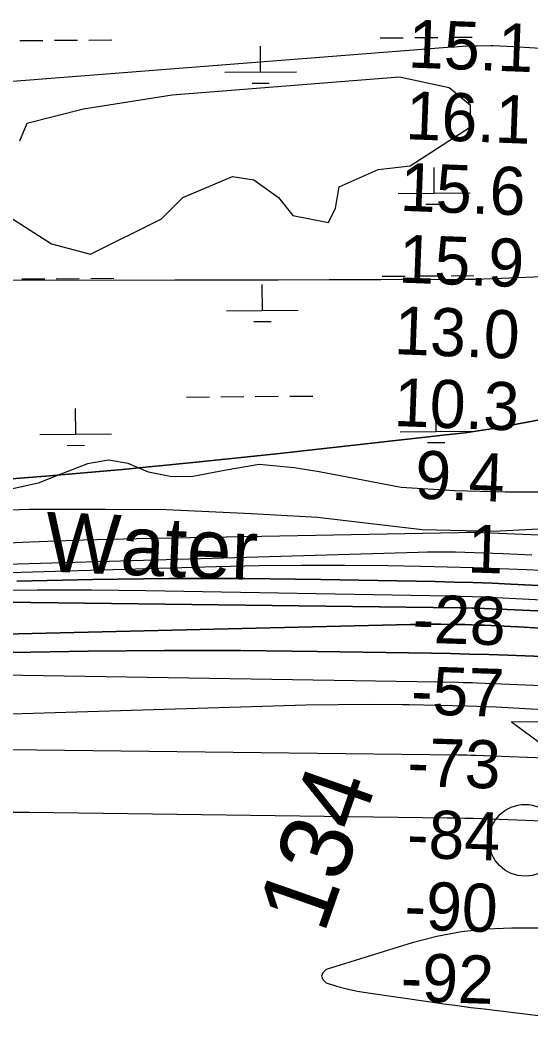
# Model space of a CAD drawing. Extents: x 3540316 to 3578335, y 553172 to 578787.
# Drawn here: x 3546126 to 3546837, y 565814 to 567208 of the extents above; entities that cross this region are included whole.
import ezdxf

# ---------------------------------------------------------------- set-up
doc = ezdxf.new("R2010")
doc.units = 0
for name, color, linetype in [('V-CHAN-NAID', 7, 'Continuous'), ('V-RIVR-EDGE', 7, 'Continuous'), ('V-RIVR-IDEN', 7, 'Continuous'), ('V-RIVR-MILE', 7, 'Continuous'), ('V-RIVR-RANG', 7, 'Continuous'), ('V-TOPO-DPTH', 7, 'Continuous'), ('V-TOPO-MAJR', 7, 'Continuous'), ('V-TOPO-MINR', 7, 'Continuous'), ('V-TOPO-WATR', 7, 'Continuous'), ('V-WETL-SWMP', 7, 'Continuous')]:
    doc.layers.add(name, color=color, linetype=linetype)

msp = doc.modelspace()

# ---------------------------------------------------------------- linework, layer by layer
at = {"layer": 'V-CHAN-NAID'}
msp.add_lwpolyline([(3546887, 566229.1), (3546810.5, 566229.7), (3546872, 566184.3)], dxfattribs=at)
at = {"layer": 'V-RIVR-EDGE'}
msp.add_lwpolyline([(3547564.9, 566487.3), (3547538, 566489.2), (3547500.6, 566487.4), (3547465.6, 566486.9), (3547417.2, 566484), (3547335.7, 566475), (3547277.5, 566472.7), (3547236.4, 566468.5), (3547157.4, 566479.1), (3547082.7, 566484.8), (3546918.5, 566501.7), (3546785.5, 566494.7), (3546685.7, 566497.4), (3546539.9, 566514.3), (3546448, 566519.5), (3546329.1, 566525.3), (3546245.2, 566525.5), (3546138.6, 566525.7), (3545988.4, 566520.6)], dxfattribs=at)
at = {"layer": 'V-RIVR-MILE'}
msp.add_circle((3546829.2, 566064.6), 50, dxfattribs=at)
at = {"layer": 'V-TOPO-DPTH'}
for points in [[(3546053.9, 566563.7), (3546161.4, 566572.2), (3546268.7, 566581.4), (3546375.9, 566591.9), (3546483.1, 566603.2), (3546727.7, 566630.4), (3546745.9, 566632.6), (3546764, 566635.1), (3546782.1, 566638.1), (3546800.1, 566641.3), (3546849.2, 566650.6)], [(3546838.8, 566462.1), (3546818.6, 566463), (3546798.5, 566463.8), (3546784.2, 566464.4), (3546771.2, 566464.9), (3546758.2, 566465.3), (3546745.2, 566465.6), (3546732.2, 566465.9), (3546719.2, 566466), (3546706.2, 566466), (3546693.2, 566465.9), (3546680.2, 566465.6), (3545898.5, 566442.7)], [(3546838.8, 566462.1), (3546818.6, 566463), (3546798.5, 566463.8), (3546784.2, 566464.4), (3546771.2, 566464.9), (3546758.2, 566465.3), (3546745.2, 566465.6), (3546732.2, 566465.9), (3546719.2, 566466), (3546706.2, 566466), (3546693.2, 566465.9), (3546680.2, 566465.6), (3545898.5, 566442.7)], [(3548154.2, 566307.3), (3548098.4, 566316.6), (3547817, 566362.2), (3547811.9, 566363), (3547806.7, 566363.6), (3547801.5, 566364.2), (3547796.2, 566364.7), (3547655.2, 566375.6), (3547579.5, 566381.2), (3547503.7, 566386.3), (3547427.8, 566390.8), (3547352, 566394.9), (3546809.6, 566421.5), (3546783.2, 566422.7), (3546756.7, 566423.7), (3546730.3, 566424.5), (3546703.8, 566425.1), (3546544.8, 566428), (3546438.9, 566429.2), (3546332.9, 566429.4), (3546227, 566428.1), (3546121.1, 566425.8)], [(3546121.1, 566425.8), (3546227, 566428.1), (3546332.9, 566429.4), (3546438.9, 566429.2), (3546544.8, 566428), (3546703.8, 566425.1), (3546730.3, 566424.5), (3546756.7, 566423.7), (3546783.2, 566422.7), (3546809.6, 566421.5), (3547352, 566394.9), (3547427.8, 566390.8), (3547503.7, 566386.3), (3547579.5, 566381.2), (3547655.2, 566375.6), (3547796.2, 566364.7), (3547801.5, 566364.2), (3547806.7, 566363.6), (3547811.9, 566363), (3547817, 566362.2), (3548098.4, 566316.6), (3548154.2, 566307.3)], [(3546028.5, 566397.4), (3546738.3, 566388.7), (3546746.9, 566388.5), (3546755.5, 566388.3), (3546764.1, 566388), (3546772.7, 566387.7), (3547162, 566370.3)], [(3547162, 566370.3), (3546772.7, 566387.7), (3546764.1, 566388), (3546755.5, 566388.3), (3546746.9, 566388.5), (3546738.3, 566388.7), (3546028.5, 566397.4)], [(3545907.9, 566347.3), (3546669.5, 566365.2), (3546683.7, 566365.5), (3546697.8, 566365.6), (3546712, 566365.6), (3546726.2, 566365.5), (3546736.3, 566365.3), (3546745.4, 566365.1), (3546754.5, 566364.9), (3546763.6, 566364.6), (3546772.7, 566364.3), (3546781.8, 566363.9), (3546791, 566363.5), (3546800.1, 566363.1), (3546809.2, 566362.6), (3546820.6, 566362), (3546835.5, 566361.2), (3546850.3, 566360.3)], [(3545907.9, 566347.3), (3546669.5, 566365.2), (3546683.7, 566365.5), (3546697.8, 566365.6), (3546712, 566365.6), (3546726.2, 566365.5), (3546736.3, 566365.3), (3546745.4, 566365.1), (3546754.5, 566364.9), (3546763.6, 566364.6), (3546772.7, 566364.3), (3546781.8, 566363.9), (3546791, 566363.5), (3546800.1, 566363.1), (3546809.2, 566362.6), (3546820.6, 566362), (3546835.5, 566361.2), (3546850.3, 566360.3)], [(3546889.4, 566319.1), (3546805.2, 566322.4), (3546778.6, 566323.4), (3546752, 566324.2), (3546725.4, 566324.8), (3546698.8, 566325.4), (3546539.5, 566327.9), (3546433.2, 566329), (3546327, 566329.2), (3546220.7, 566328.1), (3546114.5, 566326.2)], [(3546114.5, 566326.2), (3546220.7, 566328.1), (3546327, 566329.2), (3546433.2, 566329), (3546539.5, 566327.9), (3546698.8, 566325.4), (3546725.4, 566324.8), (3546752, 566324.2), (3546778.6, 566323.4), (3546805.2, 566322.4), (3546889.4, 566319.1)]]:
    msp.add_lwpolyline(points, dxfattribs=at)
at = {"layer": 'V-TOPO-MAJR'}
msp.add_lwpolyline([(3547009.3, 566273.4), (3546762.3, 566283.6), (3546755.9, 566283.9), (3546749.5, 566284.1), (3546743.1, 566284.2), (3546736.7, 566284.4), (3546013.4, 566296.2)], dxfattribs=at)
at = {"layer": 'V-TOPO-MINR'}
for points in [[(3545824.2, 567099.7), (3546721.3, 567169.8), (3546731.6, 567170.5), (3546741.9, 567171.1), (3546752.2, 567171.5), (3546762.5, 567171.9), (3546781.5, 567172.3), (3546783.9, 567172.3), (3546784.7, 567172.3), (3546813.2, 567170.8), (3546828.3, 567169.9), (3546843.3, 567168.8), (3546858.4, 567167.6), (3546873.4, 567166.2), (3547915.5, 567065), (3547926.1, 567063.5), (3547936.6, 567061.5), (3547946.9, 567058.6), (3547957.1, 567055.1), (3548274.6, 566932.1)], [(3546874.7, 566850.6), (3546796.3, 566847.3), (3546783.9, 566846.8), (3546771.6, 566846.5), (3546759.2, 566846.3), (3546746.9, 566846.1), (3546628.2, 566845.7), (3546556.5, 566845.5), (3546484.8, 566845.3), (3546413.1, 566845.2), (3546341.4, 566845.1), (3545882.5, 566844.8)], [(3546849.2, 566650.6), (3546800.1, 566641.3), (3546782.1, 566638.1), (3546764, 566635.1), (3546745.9, 566632.6), (3546727.7, 566630.4), (3546483.1, 566603.2), (3546375.9, 566591.9), (3546268.7, 566581.4), (3546161.4, 566572.2), (3546053.9, 566563.7)], [(3547639.7, 566456.6), (3546781.6, 566492.7), (3546770.4, 566493.1), (3546759.2, 566493.3), (3546747.9, 566493.3), (3546736.7, 566493.2), (3546288.4, 566484.6), (3546214.2, 566482.7), (3546139.9, 566480.2), (3546065.7, 566476.7)], [(3546953.7, 566436), (3546831, 566441.5), (3546794.2, 566443), (3546757.4, 566444.3), (3546720.7, 566445.3), (3546683.9, 566446.1), (3546638, 566446.9), (3546578.3, 566447.5), (3546518.5, 566447.6), (3546458.8, 566446.9), (3546399.1, 566445.6), (3545887.5, 566430.8)], [(3548154.2, 566307.3), (3548098.4, 566316.6), (3547817, 566362.2), (3547811.9, 566363), (3547806.7, 566363.6), (3547801.5, 566364.2), (3547796.2, 566364.7), (3547655.2, 566375.6), (3547579.5, 566381.2), (3547503.7, 566386.3), (3547427.8, 566390.8), (3547352, 566394.9), (3546809.6, 566421.5), (3546783.2, 566422.7), (3546756.7, 566423.7), (3546730.3, 566424.5), (3546703.8, 566425.1), (3546544.8, 566428), (3546438.9, 566429.2), (3546332.9, 566429.4), (3546227, 566428.1), (3546121.1, 566425.8)], [(3547673.5, 566357.3), (3546789, 566402.6), (3546772.5, 566403.3), (3546756, 566404), (3546739.5, 566404.5), (3546723, 566404.8), (3546301.1, 566412.3), (3546225.3, 566413.1), (3546149.4, 566413.2), (3546073.6, 566412.3)], [(3547162, 566370.3), (3546772.7, 566387.7), (3546764.1, 566388), (3546755.5, 566388.3), (3546746.9, 566388.5), (3546738.3, 566388.7), (3546028.5, 566397.4)], [(3546850.3, 566360.3), (3546835.5, 566361.2), (3546820.6, 566362), (3546809.2, 566362.6), (3546800.1, 566363.1), (3546791, 566363.5), (3546781.8, 566363.9), (3546772.7, 566364.3), (3546763.6, 566364.6), (3546754.5, 566364.9), (3546745.4, 566365.1), (3546736.3, 566365.3), (3546726.2, 566365.5), (3546712, 566365.6), (3546697.8, 566365.6), (3546683.7, 566365.5), (3546669.5, 566365.2), (3545907.9, 566347.3)], [(3546889.4, 566319.1), (3546805.2, 566322.4), (3546778.6, 566323.4), (3546752, 566324.2), (3546725.4, 566324.8), (3546698.8, 566325.4), (3546539.5, 566327.9), (3546433.2, 566329), (3546327, 566329.2), (3546220.7, 566328.1), (3546114.5, 566326.2)], [(3546914.7, 566243.2), (3546829.4, 566247.9), (3546789, 566249.9), (3546748.5, 566251.5), (3546708.1, 566252.5), (3546667.6, 566253.3), (3546658.7, 566253.4), (3546613.8, 566253.6), (3546568.8, 566253.5), (3546523.9, 566252.8), (3546479, 566251.7), (3545900.1, 566234)], [(3545952.9, 566192.9), (3546735.7, 566183.7), (3546741.8, 566183.6), (3546747.9, 566183.5), (3546754.1, 566183.3), (3546760.2, 566183.1), (3547000.8, 566174)], [(3546092.5, 566103.9), (3546138.8, 566103.6), (3546720.9, 566096), (3546733, 566095.8), (3546745.2, 566095.5), (3546757.3, 566095.2), (3546769.4, 566094.8), (3547662.1, 566060.5), (3547676.6, 566059.9), (3547691.2, 566059.2), (3547705.7, 566058.5), (3547720.3, 566057.7), (3547746.7, 566056.2), (3547750.7, 566056), (3547755.5, 566055.7), (3547759.4, 566055.3), (3547763.2, 566054.7), (3548136.7, 565986.2)], [(3548183, 565848.6), (3548105.2, 565854), (3548082.2, 565855.6), (3548059.3, 565857.5), (3548036.3, 565859.4), (3548013.4, 565861.5), (3547990.4, 565863.7), (3547967.5, 565865.9), (3547944.6, 565868), (3547921.6, 565870.2), (3547745.3, 565886.3), (3547731.8, 565887.6), (3547718.2, 565888.7), (3547704.6, 565889.8), (3547691, 565890.8), (3547139.2, 565931.7), (3547072.7, 565936), (3547006.2, 565939.3), (3546939.7, 565941.1), (3546873, 565942.1), (3546810.9, 565942.3), (3546775.6, 565940.9), (3546740.6, 565937.2)], [(3546740.6, 565937.2), (3546706.1, 565930.4), (3546671.9, 565921.5), (3546552.3, 565884.4), (3546547.5, 565879.8), (3546545.5, 565875.2), (3546547.4, 565870.6), (3546552.1, 565865.9), (3546566.5, 565861.5), (3546581, 565857.6), (3546595.7, 565854.5), (3546610.5, 565852), (3546697.7, 565839.3), (3546716.3, 565836.7), (3546735, 565834.2), (3546753.7, 565831.8), (3546772.3, 565829.5), (3546927, 565810.9)]]:
    msp.add_lwpolyline(points, dxfattribs=at)
at = {"layer": 'V-TOPO-WATR'}
msp.add_lwpolyline([(3546838.8, 566462.1), (3546818.6, 566463), (3546798.5, 566463.8), (3546784.2, 566464.4), (3546771.2, 566464.9), (3546758.2, 566465.3), (3546745.2, 566465.6), (3546732.2, 566465.9), (3546719.2, 566466), (3546706.2, 566466), (3546693.2, 566465.9), (3546680.2, 566465.6), (3545898.5, 566442.7)], dxfattribs=at)
at = {"layer": 'V-WETL-SWMP'}
for p, q in [((3546627.6, 567182.9), (3546659.6, 567183.1)), ((3546675.6, 567183.2), (3546707.6, 567183.5)), ((3546723.6, 567183.6), (3546755.6, 567183.8)), ((3546125.7, 567179), (3546157.7, 567179.2)), ((3546173.7, 567179.4), (3546205.7, 567179.6)), ((3546221.7, 567179.7), (3546253.7, 567180)), ((3546460.9, 567135.2), (3546460.6, 567171.2)), ((3546654.2, 567127.9), (3546337.7, 567103.1)), ((3546410.9, 567134.8), (3546510.9, 567135.6)), ((3546723.4, 567113.1), (3546654.2, 567127.9)), ((3546449, 567119.7), (3546473, 567119.9)), ((3546753.1, 567088.4), (3546723.4, 567113.1)), ((3546337.7, 567103.1), (3546214.1, 567083.4)), ((3546753.1, 567058.8), (3546753.1, 567088.4)), ((3546214.1, 567083.4), (3546135, 567063.7)), ((3546135, 567063.7), (3546125.1, 567039)), ((3546669, 567004.6), (3546753.1, 567058.8)), ((3546624.5, 566999.6), (3546669, 567004.6)), ((3546702.7, 566966.5), (3546702.4, 567002.4)), ((3546352.5, 566960.2), (3546421.8, 566989.7)), ((3546421.8, 566989.7), (3546451.4, 566984.8)), ((3546570.1, 566975), (3546624.5, 566999.6)), ((3546451.4, 566984.8), (3546486, 566960.2)), ((3546565.2, 566945.4), (3546570.1, 566975)), ((3546322.9, 566930.6), (3546352.5, 566960.2)), ((3546486, 566960.2), (3546505.8, 566935.5)), ((3546652.7, 566966.1), (3546752.7, 566966.9)), ((3546555.3, 566925.7), (3546565.2, 566945.4)), ((3546690.8, 566951), (3546714.8, 566951.2)), ((3546505.8, 566935.5), (3546555.3, 566925.7)), ((3546115.2, 566930.5), (3546169.6, 566896)), ((3546224, 566881.2), (3546322.9, 566930.6)), ((3546169.6, 566896), (3546224, 566881.2)), ((3546128.2, 566846.8), (3546160.2, 566847)), ((3546176.2, 566847.2), (3546208.2, 566847.4)), ((3546224.2, 566847.5), (3546256.2, 566847.8)), ((3546630.1, 566850.7), (3546662.1, 566850.9)), ((3546678.1, 566851), (3546710.1, 566851.3)), ((3546726.1, 566851.4), (3546758.1, 566851.7)), ((3546463.4, 566803), (3546463.2, 566839)), ((3546413.4, 566802.6), (3546513.4, 566803.4)), ((3546451.5, 566787.5), (3546475.5, 566787.7)), ((3546357.5, 566682.3), (3546389.5, 566682.5)), ((3546405.5, 566682.7), (3546437.5, 566682.9)), ((3546453.5, 566683), (3546485.5, 566683.3)), ((3546501.5, 566683.4), (3546533.5, 566683.7)), ((3546203.3, 566630.4), (3546203, 566666.4)), ((3546705.2, 566634.3), (3546704.9, 566670.3)), ((3546153.3, 566630), (3546253.3, 566630.8)), ((3546655.2, 566633.9), (3546755.2, 566634.7)), ((3546191.4, 566614.9), (3546215.4, 566615.1)), ((3546693.3, 566618.8), (3546717.3, 566619)), ((3546219.7, 566589.2), (3546182.5, 566574.6)), ((3546249, 566594.4), (3546219.7, 566589.2)), ((3546276.5, 566589.5), (3546249, 566594.4)), ((3546304.8, 566577.4), (3546276.5, 566589.5)), ((3546458.8, 566588.1), (3546413, 566580.6)), ((3546507.7, 566583.7), (3546458.8, 566588.1)), ((3546542.3, 566577.9), (3546507.7, 566583.7)), ((3546182.5, 566574.6), (3546150.9, 566562.3)), ((3546337.2, 566571.1), (3546304.8, 566577.4)), ((3546366.4, 566571.6), (3546337.2, 566571.1)), ((3546413, 566580.6), (3546366.4, 566571.6)), ((3546656.5, 566556.4), (3546542.3, 566577.9)), ((3546150.9, 566562.3), (3546107.4, 566552.4)), ((3546731.4, 566551.8), (3546656.5, 566556.4)), ((3546801.5, 566549.6), (3546731.4, 566551.8)), ((3546874.9, 566549.8), (3546801.5, 566549.6))]:
    msp.add_line(p, q, dxfattribs=at)

# ---------------------------------------------------------------- texts
at = {"layer": 'V-RIVR-IDEN'}
for s, height, rotation, p in [('Water', 83, 357.6141, (3546159.7, 566439.3)), ('134', 100, 70.71, (3546549, 565932.7))]:
    msp.add_text(s, height=height, rotation=rotation, dxfattribs=at).set_placement(p)
at = {"layer": 'V-RIVR-RANG'}
for s, rotation, p in [('15.1', 357.8383, (3546665.5, 567141.6)), ('16.1', 357.8383, (3546662, 567041.7)), ('15.6', 357.8383, (3546654.3, 566941.9)), ('15.9', 357.8383, (3546652.3, 566841.9)), ('13.0', 357.8383, (3546646.2, 566742.1)), ('10.3', 357.8383, (3546645.6, 566642)), ('9.4', 357.8383, (3546675.2, 566540.9)), ('1', 358.1249, (3546748.3, 566438)), ('-28', 358.1249, (3546671.8, 566340.4)), ('-57', 358.1249, (3546669.6, 566240.5)), ('-73', 358.1249, (3546664.7, 566140.6)), ('-84', 358.1249, (3546664.1, 566040.5)), ('-90', 358.1249, (3546660.6, 565940.6)), ('-92', 358.1249, (3546655.2, 565840.7))]:
    msp.add_text(s, height=67, rotation=rotation, dxfattribs=at).set_placement(p)

doc.saveas('drawing.dxf')
